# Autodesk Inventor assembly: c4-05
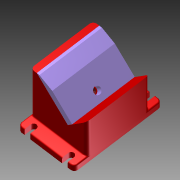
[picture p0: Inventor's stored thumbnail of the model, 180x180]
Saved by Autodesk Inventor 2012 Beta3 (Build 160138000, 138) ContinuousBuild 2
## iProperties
Created: 2010-11
Part Number: c4-05
Document SubType Name: Assembly
Designer: Beta-8540w
Author: Beta-8540w
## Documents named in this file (3)
- C:\Inventor 2012 Essentials\Assemblies\Chapter 4\c4-07.iam
- C:\Inventor 2012 Essentials\Parts\Chapter 4\c4-03.ipt
- C:\Inventor 2012 Essentials\Parts\Chapter 4\c4-04.ipt
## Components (2 placed, 2 different names)
1. c4-03:1 — Insert:1, Angle:1
2. c4-04:1 — Insert:1, Angle:1
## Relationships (2: Insert 1, Angle 1)
- Insert:1: c4-03:1 ↔ c4-04:1
- Angle:1: c4-03:1 ↔ c4-04:1
